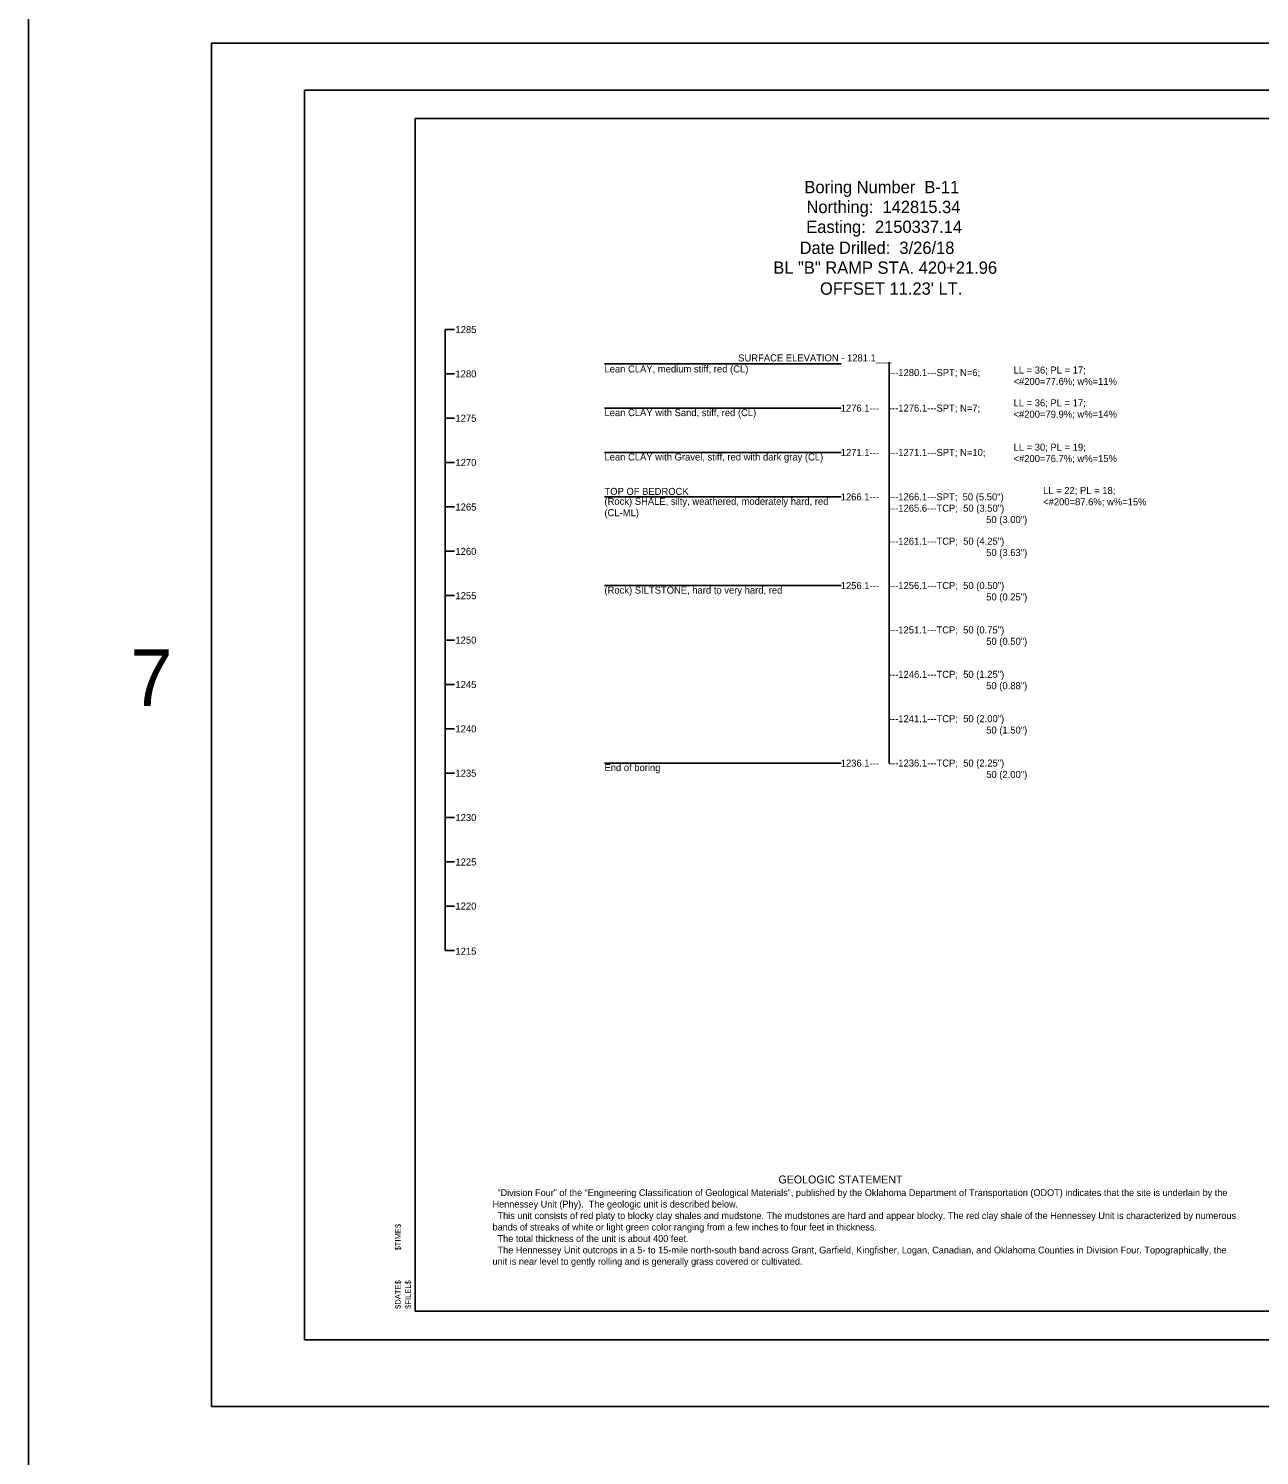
# Model space of a CAD drawing. Extents: x 2150162 to 2150245, y 143729 to 143865.
# Drawn here: x 2150203.4 to 2150225.08, y 143810.76 to 143835.89 of the extents above; entities that cross this region are included whole.
import ezdxf

# ---------------------------------------------------------------- set-up
doc = ezdxf.new("R2010")
doc.units = 0
for name, color, linetype in [('Default', 7, 'Continuous'), ('S', 7, 'Continuous'), ('SHT_Plot_Shape_Full', 7, 'Continuous'), ('SHT_Plot_Shape_Half', 7, 'Continuous'), ('SHT_Plot_Stamp', 7, 'Continuous'), ('SHT_Sheet_Border', 7, 'Continuous'), ('Text', 7, 'Continuous')]:
    doc.layers.add(name, color=color, linetype=linetype)

# ---------------------------------------------------------------- blocks, each defined once
blk = doc.blocks.new('Stamp_Plot_Stamp')
at = {"layer": 'SHT_Plot_Stamp'}
for s, p in [('$TIME$', (1.695, 1.572)), ('$DATE$', (1.695, 0.542)), ('$FILEL$', (1.873, 0.542))]:
    blk.add_text(s, height=0.1, rotation=90, dxfattribs=at).set_placement(p)

msp = doc.modelspace()

# ---------------------------------------------------------------- linework, layer by layer
at = {"layer": 'Default'}
msp.add_line((2150210.741, 143819.651), (2150210.741, 143830.588), dxfattribs=at)
for points in [[(2150210.741, 143830.588), (2150210.907, 143830.588)], [(2150213.546, 143829.983), (2150217.712, 143829.983)], [(2150218.559, 143830.01), (2150218.559, 143822.945)], [(2150210.741, 143829.807), (2150210.907, 143829.807)], [(2150213.546, 143829.202), (2150217.712, 143829.202)], [(2150210.741, 143829.026), (2150210.907, 143829.026)], [(2150213.546, 143828.421), (2150217.712, 143828.421)], [(2150210.741, 143828.244), (2150210.907, 143828.244)], [(2150210.741, 143828.244), (2150210.907, 143828.244)], [(2150213.546, 143827.639), (2150217.712, 143827.639)], [(2150210.741, 143827.463), (2150210.907, 143827.463)], [(2150210.741, 143826.682), (2150210.907, 143826.682)], [(2150213.546, 143826.077), (2150217.712, 143826.077)], [(2150210.741, 143825.901), (2150210.907, 143825.901)], [(2150210.741, 143825.119), (2150210.907, 143825.119)], [(2150210.741, 143824.338), (2150210.907, 143824.338)], [(2150210.741, 143823.557), (2150210.907, 143823.557)], [(2150213.546, 143822.952), (2150217.712, 143822.952)], [(2150210.741, 143822.776), (2150210.907, 143822.776)], [(2150210.741, 143821.994), (2150210.907, 143821.994)], [(2150210.741, 143821.213), (2150210.907, 143821.213)], [(2150210.741, 143820.432), (2150210.907, 143820.432)], [(2150210.741, 143819.651), (2150210.907, 143819.651)]]:
    msp.add_lwpolyline(points, dxfattribs=at)
at = {"layer": 'S'}
msp.add_lwpolyline([(2150203.404, 143865.061), (2150245.24, 143865.061), (2150245.24, 143729.315), (2150203.404, 143729.315)], close=True, dxfattribs=at)
at = {"layer": 'SHT_Plot_Shape_Full'}
msp.add_lwpolyline([(2150206.628, 143835.625), (2150242.628, 143835.625), (2150242.628, 143811.625), (2150206.628, 143811.625)], close=True, dxfattribs=at)
at = {"layer": 'SHT_Plot_Shape_Half'}
msp.add_lwpolyline([(2150208.265, 143834.8), (2150242.265, 143834.8), (2150242.265, 143812.8), (2150208.265, 143812.8)], close=True, dxfattribs=at)
at = {"layer": 'SHT_Sheet_Border'}
msp.add_lwpolyline([(2150241.715, 143813.3), (2150210.215, 143813.3), (2150210.215, 143834.3), (2150241.715, 143834.3)], close=True, dxfattribs=at)

# ---------------------------------------------------------------- block references
at = {"layer": 'SHT_Plot_Stamp'}
msp.add_blockref('Stamp_Plot_Stamp', (2150208.265, 143812.8), dxfattribs=at)

# ---------------------------------------------------------------- texts
at = {"layer": 'Default'}
for s, height, p in [('Boring Number  B-11', 0.217, (2150217.068, 143832.986)), ('Northing:  142815.34', 0.217, (2150217.104, 143832.636)), ('Easting:  2150337.14', 0.217, (2150217.1, 143832.286)), ('Date Drilled:  3/26/18', 0.217, (2150216.983, 143831.917)), ('BL "B" RAMP STA. 420+21.96', 0.217, (2150216.52, 143831.567)), ("OFFSET 11.23' LT.", 0.217, (2150217.342, 143831.199)), ('1285', 0.124, (2150210.922, 143830.524)), ('SURFACE ELEVATION - 1281.1___', 0.124, (2150215.902, 143830.024)), ('1280', 0.124, (2150210.922, 143829.743)), ('Lean CLAY, medium stiff, red (CL)', 0.124, (2150213.546, 143829.83)), ('---1280.1---SPT; N=6;', 0.124, (2150218.555, 143829.766)), ('LL = 36; PL = 17;', 0.124, (2150220.75, 143829.811)), ('<#200=77.6%; w%=11%', 0.124, (2150220.75, 143829.611)), ('LL = 36; PL = 17;', 0.124, (2150220.75, 143829.233)), ('1275', 0.124, (2150210.922, 143828.962)), ('Lean CLAY with Sand, stiff, red (CL)', 0.124, (2150213.546, 143829.061)), ('1276.1---', 0.124, (2150217.707, 143829.14)), ('---1276.1---SPT; N=7;', 0.124, (2150218.555, 143829.141)), ('<#200=79.9%; w%=14%', 0.124, (2150220.75, 143829.033)), ('LL = 30; PL = 19;', 0.124, (2150220.75, 143828.452)), ('Lean CLAY with Gravel, stiff, red with dark gray (CL)', 0.124, (2150213.546, 143828.28)), ('1271.1---', 0.124, (2150217.707, 143828.359)), ('---1271.1---SPT; N=10;', 0.124, (2150218.555, 143828.36)), ('<#200=76.7%; w%=15%', 0.124, (2150220.75, 143828.252)), ('1270', 0.124, (2150210.922, 143828.181)), ('LL = 22; PL = 18;', 0.124, (2150221.271, 143827.691)), ('TOP OF BEDROCK', 0.124, (2150213.546, 143827.674)), ('(Rock) SHALE, silty, weathered, moderately hard, red', 0.124, (2150213.546, 143827.499)), ('1266.1---', 0.124, (2150217.707, 143827.577)), ('---1266.1---SPT;  50 (5.50")', 0.124, (2150218.555, 143827.578)), ('<#200=87.6%; w%=15%', 0.124, (2150221.271, 143827.491)), ('1265', 0.124, (2150210.922, 143827.399)), ('(CL-ML)', 0.124, (2150213.546, 143827.299)), ('---1265.6---TCP;  50 (3.50")', 0.124, (2150218.555, 143827.378)), ('50 (3.00")', 0.124, (2150220.269, 143827.178)), ('---1261.1---TCP;  50 (4.25")', 0.124, (2150218.555, 143826.797)), ('1260', 0.124, (2150210.922, 143826.618)), ('50 (3.63")', 0.124, (2150220.269, 143826.597)), ('(Rock) SILTSTONE, hard to very hard, red', 0.124, (2150213.546, 143825.936)), ('1256.1---', 0.124, (2150217.707, 143826.015)), ('---1256.1---TCP;  50 (0.50")', 0.124, (2150218.555, 143826.016)), ('1255', 0.124, (2150210.922, 143825.837)), ('50 (0.25")', 0.124, (2150220.269, 143825.816)), ('---1251.1---TCP;  50 (0.75")', 0.124, (2150218.555, 143825.235)), ('1250', 0.124, (2150210.922, 143825.056)), ('50 (0.50")', 0.124, (2150220.269, 143825.035)), ('---1246.1---TCP;  50 (1.25")', 0.124, (2150218.555, 143824.453)), ('1245', 0.124, (2150210.922, 143824.274)), ('50 (0.88")', 0.124, (2150220.269, 143824.253)), ('---1241.1---TCP;  50 (2.00")', 0.124, (2150218.555, 143823.672)), ('1240', 0.124, (2150210.922, 143823.493)), ('50 (1.50")', 0.124, (2150220.269, 143823.472)), ('1235', 0.124, (2150210.922, 143822.712)), ('End of boring', 0.124, (2150213.546, 143822.811)), ('1236.1---', 0.124, (2150217.707, 143822.89)), ('---1236.1---TCP;  50 (2.25")', 0.124, (2150218.555, 143822.891)), ('50 (2.00")', 0.124, (2150220.269, 143822.691)), ('1230', 0.124, (2150210.922, 143821.931)), ('1225', 0.124, (2150210.922, 143821.149)), ('1220', 0.124, (2150210.922, 143820.373)), ('1215', 0.124, (2150210.922, 143819.579))]:
    msp.add_text(s, height=height, dxfattribs=at).set_placement(p)
at = {"layer": 'S'}
msp.add_text('7', height=1, dxfattribs=at).set_placement((2150205.196, 143823.955))
at = {"layer": 'Text'}
for s, height, p in [('GEOLOGIC STATEMENT', 0.14, (2150216.611, 143815.551)), ('  “Division Four” of the “Engineering Classification of Geological Materials”, published by the Oklahoma Department of Transportation (ODOT) indicates that the site is underlain by the ', 0.12, (2150211.575, 143815.329)), ('Hennessey Unit (Phy).  The geologic unit is described below. ', 0.12, (2150211.575, 143815.127)), ('  This unit consists of red platy to blocky clay shales and mudstone. The mudstones are hard and appear blocky. The red clay shale of the Hennessey Unit is characterized by numerous ', 0.12, (2150211.575, 143814.925)), ('bands of streaks of white or light green color ranging from a few inches to four feet in thickness. ', 0.12, (2150211.575, 143814.723)), ('  The total thickness of the unit is about 400 feet.', 0.12, (2150211.575, 143814.521)), ('  The Hennessey Unit outcrops in a 5- to 15-mile north-south band across Grant, Garfield, Kingfisher, Logan, Canadian, and Oklahoma Counties in Division Four. Topographically, the ', 0.12, (2150211.575, 143814.319)), ('unit is near level to gently rolling and is generally grass covered or cultivated.', 0.12, (2150211.575, 143814.119))]:
    msp.add_text(s, height=height, dxfattribs=at).set_placement(p)

doc.saveas('drawing.dxf')
